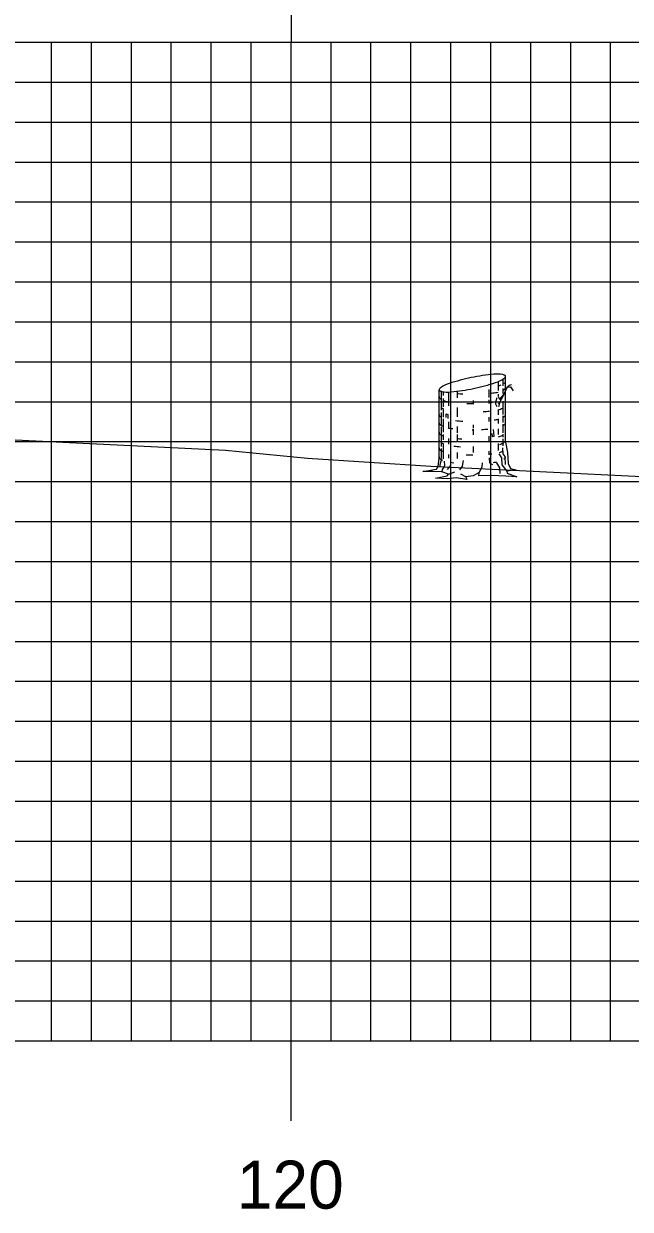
# Model space of a CAD drawing. Extents: x 1772022 to 1772366, y 442591 to 442811.
# Drawn here: x 1772061.4 to 1772076.59, y 442649.45 to 442679.13 of the extents above; entities that cross this region are included whole.
import ezdxf

# ---------------------------------------------------------------- set-up
doc = ezdxf.new("R2010")
doc.units = 0
for name, color, linetype in [('H_V ANNOTATION', 7, 'Continuous'), ('M_Trees_Conifer_Pay', 7, 'Continuous'), ('MAJOR', 7, 'Continuous'), ('MINOR', 7, 'Continuous'), ('S_Roadway_Centerline', 7, 'Continuous')]:
    doc.layers.add(name, color=color, linetype=linetype)

msp = doc.modelspace()

# ---------------------------------------------------------------- linework, layer by layer
at = {"layer": 'M_Trees_Conifer_Pay'}
for p, q in [((1772073.275, 442670.166), (1772073.275, 442669.943)), ((1772073.392, 442670.227), (1772073.392, 442670.065)), ((1772073.464, 442668.652), (1772073.464, 442670.299)), ((1772071.8, 442668.242), (1772071.8, 442669.964)), ((1772071.847, 442669.927), (1772071.847, 442669.456)), ((1772071.905, 442669.916), (1772071.905, 442669.818)), ((1772072.031, 442669.908), (1772072.031, 442669.675)), ((1772072.25, 442669.928), (1772072.25, 442669.76)), ((1772073.046, 442669.97), (1772073.046, 442669.771)), ((1772073.275, 442669.855), (1772073.275, 442669.807)), ((1772073.392, 442669.997), (1772073.392, 442669.869)), ((1772071.905, 442669.744), (1772071.905, 442669.54)), ((1772071.905, 442669.482), (1772071.905, 442669.282)), ((1772072.031, 442669.635), (1772072.031, 442669.561)), ((1772072.25, 442669.523), (1772072.25, 442669.286)), ((1772072.656, 442669.696), (1772072.656, 442669.601)), ((1772073.046, 442669.713), (1772073.046, 442669.624)), ((1772073.332, 442669.671), (1772073.281, 442669.612)), ((1772073.392, 442669.682), (1772073.392, 442669.346)), ((1772071.847, 442669.391), (1772071.847, 442669.083)), ((1772071.905, 442669.235), (1772071.905, 442668.899)), ((1772073.046, 442669.276), (1772073.046, 442669.171)), ((1772073.275, 442669.472), (1772073.275, 442669.34)), ((1772073.275, 442669.229), (1772073.275, 442669.12)), ((1772073.392, 442669.309), (1772073.392, 442669.147)), ((1772071.847, 442669.036), (1772071.847, 442668.544)), ((1772072.031, 442669.157), (1772072.031, 442669.019)), ((1772072.25, 442669.042), (1772072.25, 442668.889)), ((1772072.656, 442669.083), (1772072.656, 442669.009)), ((1772072.656, 442668.984), (1772072.656, 442668.836)), ((1772073.275, 442668.984), (1772073.275, 442668.842)), ((1772073.392, 442669.099), (1772073.392, 442668.883)), ((1772071.905, 442668.846), (1772071.905, 442668.71)), ((1772071.905, 442668.611), (1772071.905, 442668.233)), ((1772072.031, 442668.747), (1772072.031, 442668.605)), ((1772072.25, 442668.846), (1772072.25, 442668.673)), ((1772073.046, 442668.805), (1772073.046, 442668.658)), ((1772073.275, 442668.615), (1772073.275, 442668.442)), ((1772073.392, 442668.852), (1772073.392, 442668.778)), ((1772073.392, 442668.737), (1772073.392, 442668.564)), ((1772071.847, 442668.49), (1772071.847, 442668.242)), ((1772072.031, 442668.343), (1772072.031, 442668.249)), ((1772072.25, 442668.395), (1772072.25, 442668.242)), ((1772072.656, 442668.544), (1772072.656, 442668.391)), ((1772073.046, 442668.426), (1772073.046, 442668.338)), ((1772072.031, 442667.849), (1772072.193, 442667.913)), ((1772072.468, 442667.785), (1772072.342, 442667.849))]:
    msp.add_line(p, q, dxfattribs=at)
for points in [[(1772073.281, 442669.797), (1772073.317, 442669.723), (1772073.365, 442669.78), (1772073.422, 442669.849), (1772073.515, 442670.042), (1772073.579, 442670.089), (1772073.61, 442670.096)], [(1772073.295, 442669.544), (1772073.332, 442669.671), (1772073.395, 442669.787), (1772073.426, 442669.855), (1772073.495, 442670.001)], [(1772073.51, 442670.03), (1772073.585, 442670.038), (1772073.657, 442669.939)], [(1772073.247, 442669.76), (1772073.216, 442669.675), (1772073.212, 442669.608), (1772073.243, 442669.544)], [(1772071.979, 442669.27), (1772071.973, 442669.365), (1772072.016, 442669.342), (1772072.016, 442669.248)], [(1772073.118, 442668.871), (1772073.13, 442668.794), (1772073.178, 442668.805), (1772073.165, 442668.971)], [(1772073.464, 442668.652), (1772073.515, 442668.391), (1772073.531, 442668.117), (1772073.589, 442667.992), (1772073.725, 442667.961), (1772073.495, 442667.923), (1772073.495, 442667.923), (1772073.5, 442667.876), (1772073.748, 442667.782), (1772073.474, 442667.798), (1772073.118, 442667.818), (1772072.796, 442667.808), (1772072.803, 442667.891), (1772072.655, 442667.808), (1772072.468, 442667.785), (1772072.492, 442667.717), (1772072.224, 442667.761), (1772072.004, 442667.734), (1772071.711, 442667.751), (1772072, 442667.808), (1772072.031, 442667.849), (1772071.868, 442667.907), (1772071.631, 442667.918), (1772071.39, 442667.918), (1772071.732, 442667.975), (1772071.773, 442668.055), (1772071.8, 442668.242)], [(1772073.291, 442668.364), (1772073.365, 442668.259), (1772073.369, 442668.086), (1772073.495, 442667.923)], [(1772073.39, 442668.51), (1772073.395, 442668.364), (1772073.443, 442668.296), (1772073.453, 442668.097)], [(1772071.848, 442668.195), (1772071.827, 442668.117), (1772071.806, 442668.023)], [(1772071.926, 442668.175), (1772071.932, 442668.059), (1772071.878, 442667.971), (1772071.868, 442667.907)], [(1772072.088, 442668.202), (1772072.088, 442668.07), (1772072, 442667.971)], [(1772072.315, 442667.961), (1772072.382, 442668.055), (1772072.409, 442668.195)], [(1772072.803, 442667.891), (1772072.877, 442668.032), (1772072.887, 442668.133)], [(1772073.054, 442668.259), (1772073.064, 442668.133), (1772073.138, 442668.09)], [(1772073.332, 442667.87), (1772073.317, 442668.008), (1772073.243, 442668.137)]]:
    msp.add_lwpolyline(points, dxfattribs=at)
for centre, radius, start, end in [((1772072.299, 442669.358), 0.802, 108.0594, 124.2194), ((1772073.656, 442665.197), 5.179, 101.7194, 108.0594), ((1772073.656, 442665.197), 5.179, 95.3794, 101.7194), ((1772071.608, 442675.067), 5.179, 281.7194, 288.0594), ((1772073.245, 442669.555), 0.802, 79.2194, 95.3794), ((1772072.965, 442670.905), 0.802, 288.0594, 304.2194), ((1772073.133, 442670.613), 0.571, 284.4317, 292.4132), ((1772073.348, 442670.096), 0.251, 71.0501, 79.2194), ((1772073.275, 442670.45), 0.251, 304.2194, 312.3887), ((1772073.332, 442670.268), 0.172, 300, 311.2506), ((1772073.403, 442670.256), 0.0817, 56.7194, 71.0501), ((1772073.389, 442670.325), 0.0817, 312.3887, 326.7194), ((1772073.404, 442670.185), 0.0624, 311.2506, 330), ((1772073.419, 442670.28), 0.0527, 46.923, 56.7194), ((1772073.434, 442670.295), 0.0314, 34.2194, 46.923), ((1772073.413, 442670.309), 0.0527, 326.7194, 336.5158), ((1772073.42, 442670.176), 0.0441, 330, 343.9485), ((1772073.438, 442670.298), 0.0264, 23.4074, 34.2194), ((1772073.432, 442670.301), 0.0314, 336.5158, 349.2194), ((1772073.441, 442670.3), 0.0226, 11.7194, 23.4074), ((1772073.441, 442670.3), 0.0226, 0.0315, 11.7194), ((1772073.437, 442670.3), 0.0264, 349.2194, 0.0315), ((1772073.431, 442670.173), 0.0334, 343.9485, 354.2151), ((1772071.832, 442669.786), 0.0334, 163.9485, 180), ((1772071.832, 442669.786), 0.0334, 180, 196.0515), ((1772071.831, 442669.963), 0.0314, 156.5158, 169.2194), ((1772071.826, 442669.964), 0.0264, 169.2194, 180.0315), ((1772071.822, 442669.964), 0.0226, 180.0315, 191.7194), ((1772071.822, 442669.964), 0.0226, 191.7194, 203.4074), ((1772071.842, 442669.789), 0.0441, 196.0515, 210), ((1772071.851, 442669.954), 0.0527, 146.7194, 156.5158), ((1772071.826, 442669.965), 0.0264, 203.4074, 214.2194), ((1772071.83, 442669.968), 0.0314, 214.2194, 226.923), ((1772071.875, 442669.939), 0.0817, 132.3887, 146.7194), ((1772071.845, 442669.984), 0.0527, 226.923, 236.7194), ((1772071.861, 442670.008), 0.0817, 236.7194, 251.0501), ((1772071.989, 442669.814), 0.251, 124.2194, 132.3887), ((1772071.915, 442670.168), 0.251, 251.0501, 259.2194), ((1772072.018, 442670.709), 0.802, 259.2194, 275.3794), ((1772071.608, 442675.067), 5.179, 275.3794, 281.7194), ((1772072.632, 442673.976), 4.124, 264.6955, 266.7331), ((1772072.632, 442673.976), 4.124, 276.238, 278.1032), ((1772073.133, 442670.459), 0.571, 278.1032, 284.3667), ((1772073.133, 442670.459), 0.571, 297.0237, 300), ((1772073.332, 442670.113), 0.172, 300, 311.2506), ((1772073.404, 442670.031), 0.0624, 311.2506, 330), ((1772073.42, 442670.022), 0.0441, 330, 343.9485), ((1772073.431, 442670.019), 0.0334, 343.9485, 354.2151), ((1772071.858, 442669.798), 0.0624, 210, 228.7494), ((1772071.93, 442669.881), 0.172, 228.7494, 240), ((1772072.13, 442670.226), 0.571, 240, 240.3367), ((1772072.131, 442670.015), 0.571, 240, 247.0587), ((1772072.13, 442670.226), 0.571, 246.8597, 257.9846), ((1772072.631, 442673.743), 4.124, 268.0751, 270), ((1772072.631, 442673.743), 4.124, 270, 270.3581), ((1772072.631, 442673.743), 4.124, 275.7849, 277.0558), ((1772073.133, 442670.015), 0.571, 284.4493, 297.0429), ((1772073.43, 442669.575), 0.0334, 343.9485, 354.2151), ((1772071.832, 442669.339), 0.0334, 163.9485, 180), ((1772071.832, 442669.339), 0.0334, 180, 196.0515), ((1772071.842, 442669.342), 0.0441, 196.0515, 210), ((1772071.858, 442669.351), 0.0624, 210, 228.7494), ((1772071.93, 442669.434), 0.172, 228.7494, 240), ((1772072.13, 442669.779), 0.571, 240, 240.3367), ((1772072.631, 442673.296), 4.124, 264.081, 266.6676), ((1772072.632, 442673.532), 4.124, 273.7052, 275.9504), ((1772072.631, 442673.296), 4.124, 277.6125, 278.1032), ((1772073.131, 442669.779), 0.571, 278.1032, 286.9296), ((1772073.131, 442669.779), 0.571, 297.1896, 300), ((1772073.331, 442669.434), 0.172, 300, 311.2506), ((1772073.403, 442669.351), 0.0624, 311.2506, 330), ((1772073.419, 442669.342), 0.0441, 330, 343.9485), ((1772073.429, 442669.339), 0.0334, 343.9485, 354.2151), ((1772071.832, 442669.129), 0.0334, 163.9485, 180), ((1772071.832, 442669.129), 0.0334, 180, 196.0515), ((1772071.832, 442668.892), 0.0334, 163.9485, 180), ((1772071.832, 442668.892), 0.0334, 180, 196.0515), ((1772071.842, 442669.132), 0.0441, 196.0515, 210), ((1772071.842, 442668.895), 0.0441, 196.0515, 210), ((1772071.858, 442669.141), 0.0624, 210, 228.7494), ((1772071.93, 442669.224), 0.172, 228.7494, 240), ((1772072.13, 442669.569), 0.571, 240, 246.8597), ((1772072.13, 442669.569), 0.571, 259.2707, 261.8968), ((1772072.631, 442673.086), 4.124, 261.8968, 263.1474), ((1772072.631, 442673.086), 4.124, 270, 270.3581), ((1772072.631, 442673.086), 4.124, 273.1493, 275.4569), ((1772073.131, 442669.569), 0.571, 297.1896, 300), ((1772073.331, 442669.224), 0.172, 300, 311.2506), ((1772073.403, 442669.141), 0.0624, 311.2506, 330), ((1772073.419, 442669.132), 0.0441, 330, 343.9485), ((1772073.429, 442669.129), 0.0334, 343.9485, 354.2151), ((1772071.832, 442668.695), 0.0334, 163.9485, 180), ((1772071.858, 442668.904), 0.0624, 210, 228.7494), ((1772071.93, 442668.987), 0.172, 228.7494, 240), ((1772072.13, 442669.332), 0.571, 240, 246.8597), ((1772072.119, 442669.14), 0.571, 241.2369, 248.0268), ((1772072.631, 442672.85), 4.124, 264.716, 266.3193), ((1772073.131, 442669.332), 0.571, 285.3983, 297.1896), ((1772073.131, 442669.134), 0.571, 289.2907, 300), ((1772073.331, 442668.789), 0.172, 300, 311.2506), ((1772073.403, 442668.707), 0.0624, 311.2506, 330), ((1772073.419, 442668.698), 0.0441, 330, 343.9485), ((1772073.429, 442668.695), 0.0334, 343.9485, 354.2151), ((1772071.832, 442668.499), 0.0334, 163.9485, 180), ((1772071.832, 442668.499), 0.0334, 180, 196.0515), ((1772071.832, 442668.279), 0.0334, 163.9485, 180), ((1772071.842, 442668.502), 0.0441, 196.0515, 210), ((1772071.858, 442668.511), 0.0624, 210, 228.7494), ((1772071.93, 442668.594), 0.172, 228.7494, 240), ((1772072.13, 442668.939), 0.571, 240, 246.8597), ((1772072.631, 442672.652), 4.124, 263.4991, 265.8397), ((1772072.631, 442672.456), 4.124, 267.8117, 270), ((1772072.631, 442672.456), 4.124, 270, 270.1328), ((1772072.631, 442672.456), 4.124, 275.7849, 276.7896), ((1772073.131, 442668.939), 0.571, 288.5067, 297.2721), ((1772071.832, 442668.279), 0.0334, 180, 196.0515), ((1772071.842, 442668.282), 0.0441, 196.0515, 210), ((1772071.858, 442668.291), 0.0624, 210, 228.7494), ((1772071.93, 442668.373), 0.172, 228.7494, 240), ((1772072.13, 442668.718), 0.571, 240, 244.5314), ((1772072.631, 442672.236), 4.124, 262.4438, 263.512), ((1772072.631, 442672.236), 4.124, 277.3684, 278.1032), ((1772073.131, 442668.718), 0.571, 278.1032, 281.637), ((1772073.331, 442668.373), 0.172, 300, 311.2506), ((1772073.403, 442668.291), 0.0624, 311.2506, 330), ((1772073.419, 442668.282), 0.0441, 330, 343.9485), ((1772073.429, 442668.279), 0.0334, 343.9485, 354.2151)]:
    msp.add_arc(centre, radius, start, end, dxfattribs=at)
at = {"layer": 'MAJOR'}
for p, q in [((1772068.094, 442680.669), (1772068.094, 442678.665)), ((1772048.094, 442678.665), (1772328.094, 442678.665)), ((1772048.094, 442678.665), (1772328.094, 442678.665)), ((1772068.094, 442653.665), (1772068.094, 442678.665)), ((1772048.094, 442673.665), (1772328.094, 442673.665)), ((1772048.094, 442668.665), (1772328.094, 442668.665)), ((1772048.094, 442663.665), (1772328.094, 442663.665)), ((1772048.094, 442658.665), (1772328.094, 442658.665)), ((1772048.094, 442653.665), (1772328.094, 442653.665)), ((1772048.094, 442653.665), (1772328.094, 442653.665)), ((1772068.094, 442651.661), (1772068.094, 442653.665))]:
    msp.add_line(p, q, dxfattribs=at)
at = {"layer": 'MINOR'}
for p, q in [((1772062.094, 442653.665), (1772062.094, 442678.665)), ((1772063.094, 442653.665), (1772063.094, 442678.665)), ((1772064.094, 442653.665), (1772064.094, 442678.665)), ((1772065.094, 442653.665), (1772065.094, 442678.665)), ((1772066.094, 442653.665), (1772066.094, 442678.665)), ((1772067.094, 442653.665), (1772067.094, 442678.665)), ((1772069.094, 442653.665), (1772069.094, 442678.665)), ((1772070.094, 442653.665), (1772070.094, 442678.665)), ((1772071.094, 442653.665), (1772071.094, 442678.665)), ((1772072.094, 442653.665), (1772072.094, 442678.665)), ((1772073.094, 442653.665), (1772073.094, 442678.665)), ((1772074.094, 442653.665), (1772074.094, 442678.665)), ((1772075.094, 442653.665), (1772075.094, 442678.665)), ((1772076.094, 442653.665), (1772076.094, 442678.665)), ((1772048.094, 442677.665), (1772328.094, 442677.665)), ((1772048.094, 442676.665), (1772328.094, 442676.665)), ((1772048.094, 442675.665), (1772328.094, 442675.665)), ((1772048.094, 442674.665), (1772328.094, 442674.665)), ((1772048.094, 442672.665), (1772328.094, 442672.665)), ((1772048.094, 442671.665), (1772328.094, 442671.665)), ((1772048.094, 442670.665), (1772328.094, 442670.665)), ((1772048.094, 442669.665), (1772328.094, 442669.665)), ((1772048.094, 442667.665), (1772328.094, 442667.665)), ((1772048.094, 442666.665), (1772328.094, 442666.665)), ((1772048.094, 442665.665), (1772328.094, 442665.665)), ((1772048.094, 442664.665), (1772328.094, 442664.665)), ((1772048.094, 442662.665), (1772328.094, 442662.665)), ((1772048.094, 442661.665), (1772328.094, 442661.665)), ((1772048.094, 442660.665), (1772328.094, 442660.665)), ((1772048.094, 442659.665), (1772328.094, 442659.665)), ((1772048.094, 442657.665), (1772328.094, 442657.665)), ((1772048.094, 442656.665), (1772328.094, 442656.665)), ((1772048.094, 442655.665), (1772328.094, 442655.665)), ((1772048.094, 442654.665), (1772328.094, 442654.665))]:
    msp.add_line(p, q, dxfattribs=at)
at = {"layer": 'S_Roadway_Centerline'}
msp.add_lwpolyline([(1772048.094, 442669.441), (1772056.429, 442668.948), (1772066.454, 442668.448), (1772068.508, 442668.251), (1772071.595, 442668.049), (1772079.781, 442667.654), (1772085.527, 442667.353), (1772090.854, 442667.407), (1772097.533, 442666.923), (1772106.7, 442666.846), (1772114.442, 442666.922), (1772125.595, 442666.322), (1772126.179, 442666.296), (1772126.588, 442666.301), (1772137.909, 442665.932)], dxfattribs=at)

# ---------------------------------------------------------------- texts
at = {"layer": 'H_V ANNOTATION'}
msp.add_text('120', height=1.2, dxfattribs=at).set_placement((1772066.734, 442649.465))

doc.saveas('drawing.dxf')
